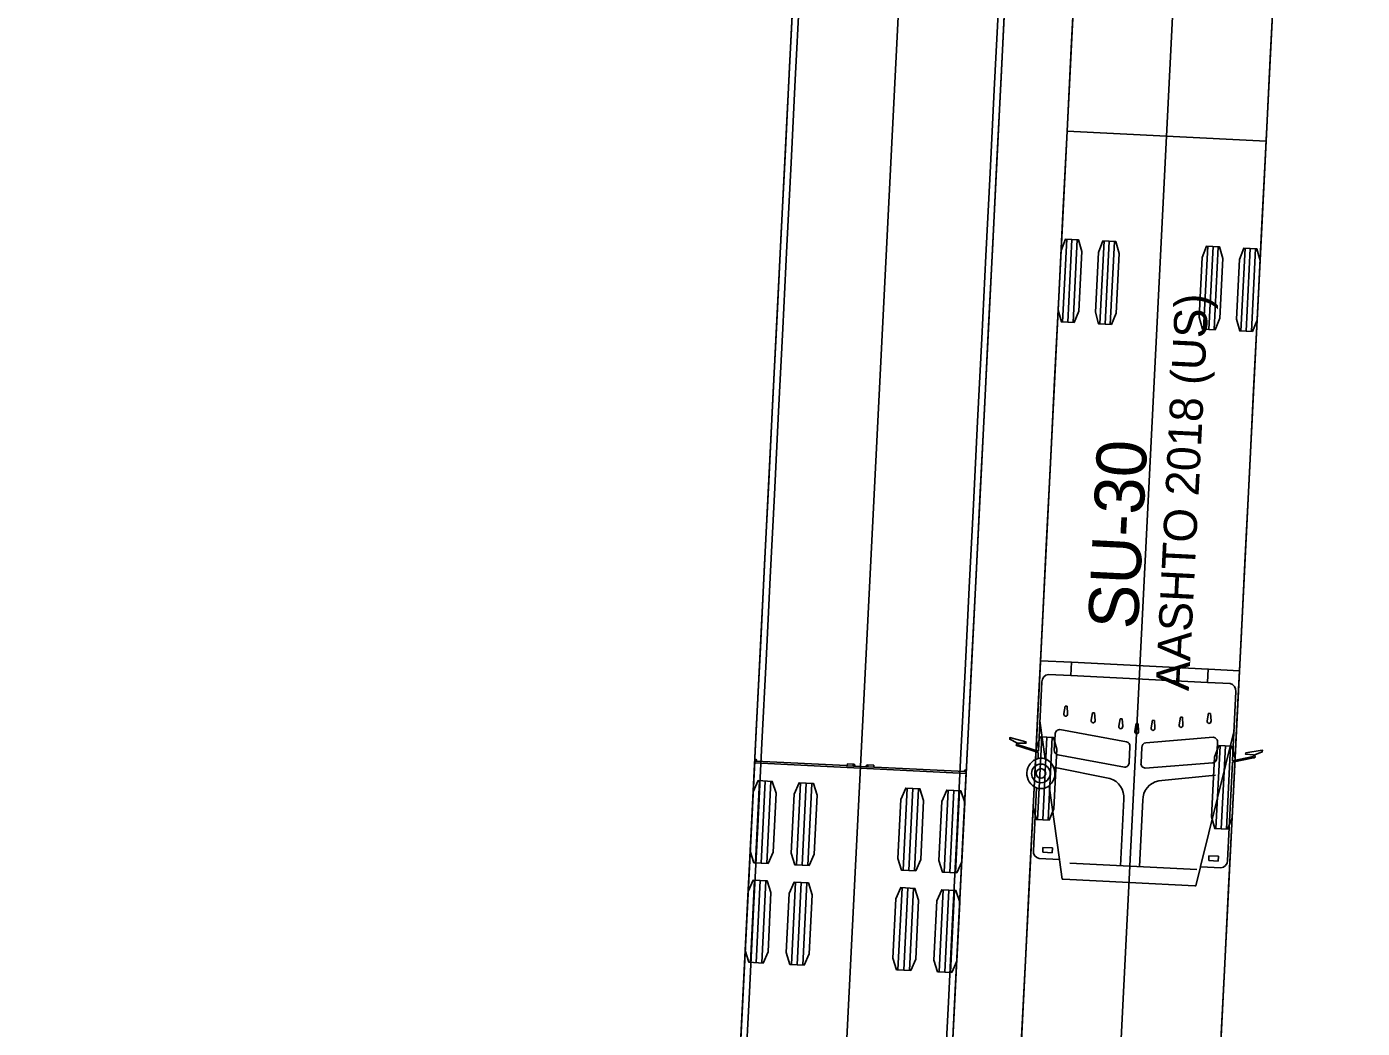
# Model space of a CAD drawing. Extents: x 260275 to 261282, y 610916 to 614143.
# Drawn here: x 260986.2 to 261039.9, y 611791.3 to 611831.5 of the extents above; entities that cross this region are included whole.
import ezdxf

# ---------------------------------------------------------------- set-up
doc = ezdxf.new("R2010")
doc.units = 0
doc.layers.add('GE_X_Alignment', color=7, linetype='Continuous')
doc.layers.add('UT_X_Water_Cells', color=7, linetype='Continuous')

msp = doc.modelspace()

# ---------------------------------------------------------------- linework, layer by layer
at = {"layer": 'GE_X_Alignment'}
msp.add_line((260986.249, 610915.954), (261148.276, 614142.838), dxfattribs=at)
at = {"layer": 'UT_X_Water_Cells'}
for p, q in [((261044.031, 612066.726), (261023.69, 611661.632)), ((261031.95, 612045.486), (261010.925, 611626.741)), ((261027.826, 611819.602), (261027.993, 611822.931)), ((261028.034, 611819.592), (261028.201, 611822.921)), ((261028.242, 611819.581), (261028.409, 611822.91)), ((261029.324, 611819.527), (261029.491, 611822.856)), ((261029.532, 611819.516), (261029.699, 611822.845)), ((261029.74, 611819.506), (261029.907, 611822.835)), ((261033.485, 611819.318), (261033.653, 611822.647)), ((261033.694, 611819.307), (261033.861, 611822.637)), ((261033.902, 611819.297), (261034.069, 611822.626)), ((261034.984, 611819.243), (261035.151, 611822.572)), ((261035.192, 611819.232), (261035.359, 611822.561)), ((261035.4, 611819.222), (261035.567, 611822.551)), ((261028.187, 611805.947), (261033.672, 611805.671)), ((261028.161, 611805.416), (261033.646, 611805.14)), ((261027.87, 611803.889), (261027.921, 611804.186)), ((261027.921, 611804.186), (261028.003, 611804.182)), ((261028.003, 611804.182), (261028.024, 611803.881)), ((261028.975, 611803.623), (261029.026, 611803.92)), ((261029.026, 611803.92), (261029.108, 611803.916)), ((261029.108, 611803.916), (261029.129, 611803.615)), ((261033.628, 611803.6), (261033.679, 611803.897)), ((261033.679, 611803.897), (261033.761, 611803.893)), ((261026.914, 611803.6), (261027.13, 611802.067)), ((261030.082, 611803.385), (261030.133, 611803.682)), ((261030.133, 611803.682), (261030.215, 611803.678)), ((261030.215, 611803.678), (261030.236, 611803.377)), ((261030.721, 611803.184), (261030.772, 611803.482)), ((261030.772, 611803.482), (261030.854, 611803.477)), ((261030.854, 611803.477), (261030.875, 611803.176)), ((261031.377, 611803.32), (261031.427, 611803.617)), ((261031.427, 611803.617), (261031.51, 611803.613)), ((261031.51, 611803.613), (261031.531, 611803.312)), ((261032.502, 611803.432), (261032.552, 611803.743)), ((261032.552, 611803.743), (261032.635, 611803.739)), ((261032.635, 611803.739), (261032.656, 611803.424)), ((261033.761, 611803.893), (261033.782, 611803.592)), ((261026.823, 611799.627), (261026.99, 611802.956)), ((261027.031, 611799.617), (261027.198, 611802.946)), ((261027.239, 611799.606), (261027.406, 611802.935)), ((261027.522, 611803.05), (261027.491, 611802.434)), ((261030.387, 611802.757), (261027.713, 611803.243)), ((261031.164, 611802.718), (261033.873, 611802.934)), ((261034.704, 611803.209), (261033.364, 611797.742)), ((261030.497, 611801.931), (261030.528, 611802.547)), ((261030.972, 611801.908), (261031.003, 611802.523)), ((261033.981, 611799.268), (261034.148, 611802.597)), ((261034.044, 611802.723), (261034.013, 611802.107)), ((261034.189, 611799.257), (261034.356, 611802.586)), ((261034.397, 611799.247), (261034.564, 611802.576)), ((261015.465, 611801.91), (261023.954, 611801.484)), ((261019.182, 611801.794), (261019.448, 611801.781)), ((261019.972, 611801.755), (261019.449, 611801.781)), ((261019.713, 611801.768), (261019.709, 611801.697)), ((261019.978, 611801.754), (261020.244, 611801.741)), ((261027.632, 611802.225), (261030.305, 611801.739)), ((261033.852, 611801.913), (261031.143, 611801.697)), ((261029.72, 611801.281), (261027.464, 611801.742)), ((261031.68, 611801.183), (261033.959, 611801.414)), ((261015.493, 611797.895), (261015.658, 611801.191)), ((261015.722, 611797.883), (261015.887, 611801.179)), ((261015.95, 611797.872), (261016.116, 611801.168)), ((261017.141, 611797.812), (261017.306, 611801.108)), ((261017.369, 611797.801), (261017.535, 611801.096)), ((261017.598, 611797.789), (261017.764, 611801.085)), ((261021.419, 611797.597), (261021.584, 611800.893)), ((261021.647, 611797.586), (261021.813, 611800.882)), ((261021.876, 611797.574), (261022.042, 611800.87)), ((261023.066, 611797.515), (261023.232, 611800.81)), ((261023.295, 611797.503), (261023.461, 611800.799)), ((261023.524, 611797.492), (261023.69, 611800.787)), ((261026.778, 611800.901), (261026.652, 611798.382)), ((261027.282, 611800.992), (261027.7, 611798.026)), ((261030.143, 611797.78), (261030.277, 611800.445)), ((261030.908, 611797.742), (261031.042, 611800.407)), ((261027.035, 611798.516), (261027.025, 611798.322)), ((261027.025, 611798.322), (261027.403, 611798.303)), ((261027.413, 611798.497), (261027.035, 611798.516)), ((261027.403, 611798.303), (261027.413, 611798.497)), ((261033.687, 611797.987), (261033.697, 611798.181)), ((261033.697, 611798.181), (261034.075, 611798.162)), ((261034.075, 611798.162), (261034.065, 611797.968)), ((261028.109, 611797.882), (261033.208, 611797.626)), ((261034.065, 611797.968), (261033.687, 611797.987)), ((261015.292, 611793.9), (261015.458, 611797.196)), ((261015.521, 611793.888), (261015.686, 611797.184)), ((261015.75, 611793.877), (261015.915, 611797.173)), ((261016.94, 611793.817), (261017.105, 611797.113)), ((261017.169, 611793.806), (261017.334, 611797.102)), ((261017.398, 611793.794), (261017.563, 611797.09)), ((261021.218, 611793.602), (261021.383, 611796.898)), ((261021.447, 611793.591), (261021.612, 611796.887)), ((261021.676, 611793.579), (261021.841, 611796.875)), ((261022.866, 611793.52), (261023.031, 611796.815)), ((261023.095, 611793.508), (261023.26, 611796.804)), ((261023.324, 611793.497), (261023.489, 611796.792))]:
    msp.add_line(p, q, dxfattribs=at)
for points in [[(261009.34, 611680.102), (261030.965, 612110.617)], [(261039.447, 612110.045), (261018.12, 611685.301)], [(261020.965, 611687.133), (261041.34, 612092.893)], [(261049.322, 612092.345), (261028.546, 611678.469)], [(261028.337, 611833.926), (261028.169, 611830.597), (261028.002, 611827.269), (261027.835, 611823.94), (261027.668, 611820.611), (261027.501, 611817.283), (261027.334, 611813.954), (261027.167, 611810.625), (261026.999, 611807.297), (261026.832, 611803.968), (261026.665, 611800.64), (261026.498, 611797.311), (261026.331, 611793.982), (261026.164, 611790.654)], [(261028.336, 611833.923), (261028.169, 611830.594), (261028.002, 611827.265), (261027.835, 611823.937), (261027.668, 611820.608), (261027.501, 611817.28), (261027.334, 611813.951), (261027.166, 611810.622), (261026.999, 611807.294), (261026.832, 611803.965), (261026.665, 611800.636), (261026.498, 611797.308), (261026.331, 611793.979), (261026.164, 611790.651)], [(261036.326, 611833.525), (261036.159, 611830.196), (261035.992, 611826.867), (261035.825, 611823.539), (261035.658, 611820.21), (261035.491, 611816.882), (261035.324, 611813.553), (261035.157, 611810.224), (261034.989, 611806.896), (261034.822, 611803.567), (261034.655, 611800.238), (261034.488, 611796.91), (261034.321, 611793.581), (261034.154, 611790.253)], [(261036.326, 611833.521), (261036.159, 611830.193), (261035.992, 611826.864), (261035.825, 611823.536), (261035.658, 611820.207), (261035.491, 611816.878), (261035.323, 611813.55), (261035.156, 611810.221), (261034.989, 611806.893), (261034.822, 611803.564), (261034.655, 611800.235), (261034.488, 611796.907), (261034.321, 611793.578), (261034.154, 611790.249)], [(261017.035, 611833.173), (261016.867, 611829.845), (261016.7, 611826.516), (261016.533, 611823.187), (261016.366, 611819.859), (261016.199, 611816.53), (261016.032, 611813.201), (261015.865, 611809.873), (261015.697, 611806.544), (261015.53, 611803.216), (261015.363, 611799.887), (261015.196, 611796.558), (261015.029, 611793.23), (261014.862, 611789.901)], [(261017.259, 611832.653), (261017.092, 611829.324), (261016.924, 611825.995), (261016.757, 611822.667), (261016.59, 611819.338), (261016.423, 611816.009), (261016.256, 611812.681), (261016.089, 611809.352), (261015.922, 611806.023), (261015.755, 611802.695), (261015.587, 611799.366), (261015.42, 611796.038), (261015.253, 611792.709), (261015.086, 611789.38)], [(261025.524, 611832.747), (261025.357, 611829.418), (261025.19, 611826.09), (261025.022, 611822.761), (261024.855, 611819.433), (261024.688, 611816.104), (261024.521, 611812.775), (261024.354, 611809.447), (261024.187, 611806.118), (261024.02, 611802.789), (261023.853, 611799.461), (261023.685, 611796.132), (261023.518, 611792.803), (261023.351, 611789.475)], [(261025.249, 611832.252), (261025.082, 611828.923), (261024.914, 611825.594), (261024.747, 611822.266), (261024.58, 611818.937), (261024.413, 611815.608), (261024.246, 611812.28), (261024.079, 611808.951), (261023.912, 611805.622), (261023.744, 611802.294), (261023.577, 611798.965), (261023.41, 611795.636), (261023.243, 611792.308), (261023.076, 611788.979)], [(261034.544, 611805.095), (261033.649, 611805.14), (261033.646, 611805.144), (261033.672, 611805.67), (261033.683, 611805.671), (261034.925, 611805.609), (261035.992, 611826.868), (261031.997, 611827.069), (261028.002, 611827.27), (261026.935, 611806.01), (261028.176, 611805.947), (261028.187, 611805.946), (261028.161, 611805.42), (261028.157, 611805.416), (261027.262, 611805.461)], [(261026.992, 611805.159), (261026.853, 611802.388), (261026.848, 611802.376), (261026.043, 611802.637), (261026.042, 611802.637)], [(261035.475, 611802.163), (261035.475, 611802.163), (261034.647, 611801.985), (261034.643, 611801.997), (261034.782, 611804.768)], [(261026.032, 611802.657), (261026.034, 611802.702), (261026.034, 611802.702), (261026.352, 611802.695), (261026.354, 611802.695), (261026.357, 611802.75), (261026.354, 611802.752), (261025.706, 611802.924), (261025.703, 611802.924), (261025.7, 611802.859), (261025.988, 611802.713), (261025.988, 611802.712), (261025.986, 611802.665)], [(261026.023, 611802.59), (261026.024, 611802.59), (261026.843, 611802.322), (261026.849, 611802.31), (261026.838, 611802.082)], [(261035.534, 611802.186), (261035.537, 611802.233), (261035.537, 611802.233), (261035.838, 611802.35), (261035.841, 611802.415), (261035.838, 611802.415), (261035.176, 611802.309), (261035.173, 611802.308), (261035.17, 611802.252), (261035.173, 611802.252), (261035.49, 611802.227), (261035.49, 611802.227), (261035.487, 611802.183)], [(261015.491, 611801.98), (261015.468, 611801.981), (261013.065, 611754.112), (261017.309, 611753.898), (261021.554, 611753.685), (261023.958, 611801.554), (261023.935, 611801.555)], [(261019.453, 611801.851), (261019.187, 611801.865), (261019.186, 611801.864), (261019.182, 611801.794), (261019.147, 611801.796), (261015.516, 611801.978), (261015.515, 611801.978)], [(261023.911, 611801.557), (261023.91, 611801.557), (261020.279, 611801.739), (261020.244, 611801.741), (261020.247, 611801.811), (261020.246, 611801.811), (261019.98, 611801.825)], [(261034.442, 611797.991), (261034.639, 611801.919), (261034.647, 611801.931), (261035.489, 611802.115), (261035.489, 611802.115)], [(261026.89, 611798.067), (261027.696, 611798.026), (261027.701, 611798.021), (261027.811, 611797.243), (261027.853, 611797.239), (261030.493, 611797.107), (261033.133, 611796.974), (261033.175, 611796.974), (261033.362, 611797.737), (261033.367, 611797.741), (261034.174, 611797.701)]]:
    msp.add_lwpolyline(points, dxfattribs=at)
for points in [[(261028.294, 611819.579), (261027.774, 611819.605), (261027.641, 611820.079), (261027.762, 611822.476), (261027.941, 611822.934), (261028.461, 611822.908), (261028.594, 611822.434), (261028.474, 611820.037)], [(261029.792, 611819.503), (261029.272, 611819.529), (261029.139, 611820.003), (261029.26, 611822.4), (261029.44, 611822.859), (261029.959, 611822.832), (261030.092, 611822.359), (261029.972, 611819.962)], [(261033.953, 611819.294), (261033.434, 611819.32), (261033.301, 611819.794), (261033.421, 611822.191), (261033.601, 611822.65), (261034.12, 611822.623), (261034.253, 611822.15), (261034.133, 611819.753)], [(261035.451, 611819.219), (261034.932, 611819.245), (261034.799, 611819.719), (261034.919, 611822.116), (261035.099, 611822.574), (261035.618, 611822.548), (261035.752, 611822.074), (261035.631, 611819.677)], [(261027.291, 611799.604), (261026.771, 611799.63), (261026.638, 611800.104), (261026.759, 611802.501), (261026.939, 611802.959), (261027.458, 611802.933), (261027.591, 611802.459), (261027.471, 611800.062)], [(261034.448, 611799.244), (261033.929, 611799.27), (261033.796, 611799.744), (261033.916, 611802.141), (261034.096, 611802.6), (261034.615, 611802.573), (261034.749, 611802.1), (261034.628, 611799.703)], [(261016.007, 611797.869), (261015.436, 611797.898), (261015.287, 611798.368), (261015.406, 611800.741), (261015.601, 611801.194), (261016.173, 611801.165), (261016.322, 611800.695), (261016.202, 611798.322)], [(261017.655, 611797.786), (261017.084, 611797.815), (261016.935, 611798.285), (261017.054, 611800.658), (261017.249, 611801.111), (261017.821, 611801.082), (261017.97, 611800.612), (261017.85, 611798.239)], [(261021.933, 611797.571), (261021.362, 611797.6), (261021.213, 611798.07), (261021.332, 611800.443), (261021.527, 611800.896), (261022.099, 611800.867), (261022.247, 611800.397), (261022.128, 611798.024)], [(261023.581, 611797.489), (261023.01, 611797.517), (261022.861, 611797.987), (261022.98, 611800.36), (261023.175, 611800.813), (261023.746, 611800.785), (261023.895, 611800.315), (261023.776, 611797.942)], [(261015.807, 611793.874), (261015.235, 611793.903), (261015.086, 611794.373), (261015.205, 611796.746), (261015.401, 611797.199), (261015.972, 611797.17), (261016.121, 611796.7), (261016.002, 611794.327)], [(261017.454, 611793.791), (261016.883, 611793.82), (261016.734, 611794.29), (261016.853, 611796.663), (261017.049, 611797.116), (261017.62, 611797.087), (261017.769, 611796.617), (261017.65, 611794.244)], [(261021.732, 611793.577), (261021.161, 611793.605), (261021.012, 611794.075), (261021.131, 611796.448), (261021.327, 611796.901), (261021.898, 611796.872), (261022.047, 611796.402), (261021.928, 611794.029)], [(261023.38, 611793.494), (261022.809, 611793.522), (261022.66, 611793.993), (261022.779, 611796.366), (261022.975, 611796.818), (261023.546, 611796.79), (261023.695, 611796.32), (261023.576, 611793.947)]]:
    msp.add_lwpolyline(points, close=True, dxfattribs=at)
for centre, radius in [((261015.504, 611802.013), 0.0266), ((261026.953, 611801.484), 0.374), ((261023.925, 611801.59), 0.0266), ((261026.953, 611801.484), 0.193)]:
    msp.add_circle(centre, radius, dxfattribs=at)
for centre, radius, start, end in [((261027.314, 611805.143), 0.323, 99.2771, 177.1255), ((261034.46, 611804.784), 0.323, 357.1255, 74.9739), ((261027.958, 611803.866), 0.091, 165.4421, 259.6059), ((261027.934, 611803.867), 0.0909, 274.6094, 8.8446), ((261029.063, 611803.6), 0.091, 165.4421, 259.6059), ((261029.039, 611803.601), 0.0909, 274.6094, 8.8446), ((261030.17, 611803.362), 0.091, 165.4421, 259.6059), ((261030.146, 611803.363), 0.0909, 274.6094, 8.8446), ((261032.589, 611803.423), 0.0909, 165.4064, 259.6416), ((261032.566, 611803.424), 0.091, 274.6451, 8.8089), ((261033.716, 611803.577), 0.0909, 165.4064, 259.6416), ((261033.692, 611803.578), 0.091, 274.6451, 8.8089), ((261027.706, 611803.059), 0.184, 87.7181, 182.5893), ((261030.809, 611803.161), 0.091, 165.4421, 259.6059), ((261030.785, 611803.162), 0.091, 274.6451, 8.8089), ((261031.465, 611803.297), 0.0909, 165.4064, 259.6416), ((261031.441, 611803.298), 0.091, 274.6451, 8.8089), ((261033.862, 611802.75), 0.184, 351.6617, 86.5329), ((261026.006, 611802.628), 0.0418, 117.6187, 294.6336), ((261026, 611802.628), 0.0434, 11.039, 41.7118), ((261027.682, 611802.411), 0.193, 173.0686, 254.9831), ((261030.337, 611802.571), 0.193, 353.0637, 74.988), ((261031.195, 611802.527), 0.193, 99.263, 181.1873), ((261015.504, 611802.013), 0.0363, 286.8861, 248.0487), ((261019.452, 611801.816), 0.0354, 91.417, 263.6025), ((261019.452, 611801.816), 0.0352, 266.5234, 87.1099), ((261019.978, 611801.79), 0.0352, 87.1411, 267.7276), ((261019.978, 611801.789), 0.0352, 266.913, 89.5524), ((261027.02, 611801.481), 0.628, 106.8788, 247.3705), ((261026.957, 611801.571), 0.524, 49.3845, 103.1846), ((261026.884, 611801.495), 0.63, 356.4803, 48.8831), ((261030.313, 611801.923), 0.184, 267.7236, 2.5838), ((261031.154, 611801.881), 0.184, 171.6672, 266.5274), ((261033.821, 611802.103), 0.193, 279.2679, 1.1824), ((261035.517, 611802.151), 0.0434, 132.5392, 163.212), ((261035.511, 611802.151), 0.0418, 239.6174, 56.6324), ((261023.925, 611801.59), 0.0363, 286.2023, 247.3649), ((261026.884, 611801.48), 0.629, 309.1711, 357.8604), ((261029.51, 611800.537), 0.773, 353.1509, 74.235), ((261026.949, 611801.398), 0.526, 251.0707, 309.3167), ((261031.815, 611800.421), 0.773, 100.016, 181.1001), ((261026.931, 611798.345), 0.282, 172.4977, 261.5771), ((261034.161, 611797.982), 0.282, 272.6739, 1.7533)]:
    msp.add_arc(centre, radius, start, end, dxfattribs=at)

# ---------------------------------------------------------------- texts
for s, height, p in [('AASHTO 2018 (US)', 1.33333, (261032.887, 611804.782)), ('SU-30', 2, (261030.842, 611807.245))]:
    msp.add_text(s, height=height, rotation=87.1255, dxfattribs=at).set_placement(p)

doc.saveas('drawing.dxf')
